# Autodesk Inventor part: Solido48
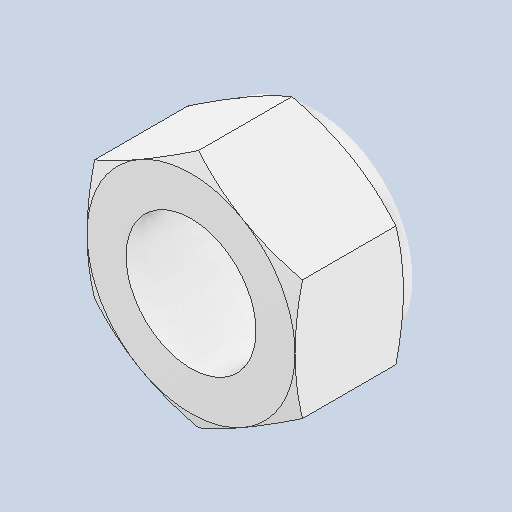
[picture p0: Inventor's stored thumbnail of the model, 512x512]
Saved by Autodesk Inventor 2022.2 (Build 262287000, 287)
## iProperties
Created: 2024-10
Part Number: Solido48
Material: Generico
Document SubType Name: Modeling
Designer: 18907419
Density: 1 g/cm^3
Appearance: Default
Author: 18907419
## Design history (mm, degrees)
feature "Solido48"
node "Solido1"
